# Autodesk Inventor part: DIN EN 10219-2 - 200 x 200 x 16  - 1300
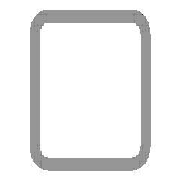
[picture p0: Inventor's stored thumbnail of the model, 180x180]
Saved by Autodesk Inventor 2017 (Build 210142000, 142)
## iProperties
Created: 2017-11
Part Number: DIN EN 10219-2 - 200 x 200 x 16  - 1300
Material: Steel, Mild
Description: Cold formed welded structural hollow sections of non-alloy and fine grain structural steel
Document SubType Name: Modeling
Standard: DIN
Designer: iusti
Standard Revision: 2006-07
Standards Organization: DIN
Language: en-US
Size Designation: 200 x 200 x 16
Categories: <MemberInstance><Categories><Category DisplayName="Structural Shapes" InternalName="089c4875-fa83-4c05-b084-43b9cc11f5ed" Mnemonic="GRDR"><CategoryParameter Dis
Stock Number: 200 x 200 x 16
Mass: 108961 g
Surface Area: 17564.1 cm^2
Volume: 13880.4 cm^3
Density: 7.85 g/cm^3
Appearance: Semi-Polished
_CCFamilyMember: 103
_CCFamilyDisplayName: DIN EN 10219-2 (Square Hollow Section - Cold Formed) - Cold formed welded structural hollow sections of non-alloy and fine grain structural steel
_FrameMemberDoc: Frame Member File
_Version: 15.0.0
_GetPNFromCC: 1
G_L: 1300.000 mm
G_W: 200.000 mm
G_H: 200.000 mm
+5245FDE4-FC26-48DD-8D5F-DB9AF3ABDA78+CUTDETAIL1: Cut
+5EC8F8CE-D404-4871-B3D9-14F147CC6C7E+CUTDETAIL2: Cut
IsCustomPart: 1
Author: iusti
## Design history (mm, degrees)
node "Start plane"
node "End plane"
sketch "Sketch"
  geometry: L1 (-100, -52)-(-100, 52); L2 (-52, 100)-(52, 100); L3 (100, 52)-(100, -52); L4 (52, -100)-(-52, -100); L5 (-52, 84)-(52, 84); L6 (84, 52)-(84, -52); L7 (52, -84)-(-52, -84); L8 (-84, -52)-(-84, 52); L9 (0, 153.918)-(0, -153.918) reference; L10 (-153.918, 0)-(153.918, 0) reference; A1 r 48 centre (-52, -52) between (-100, -52) and (-52, -100); A2 r 48 centre (-52, 52) between (-52, 100) and (-100, 52); A3 r 48 centre (52, 52) between (100, 52) and (52, 100); A4 r 48 centre (52, -52) between (52, -100) and (100, -52); A5 r 32 centre (-52, 52) between (-52, 84) and (-84, 52); A6 r 32 centre (52, 52) between (84, 52) and (52, 84); A7 r 32 centre (52, -52) between (52, -84) and (84, -52); A8 r 32 centre (-52, -52) between (-84, -52) and (-52, -84)
  constraints: 16 end point, 16 point on circle, 8 centre point, 8 tangent, 4 parallel, 3 equal radius, 2 perpendicular, 7 other
  dimensions: "d7" = 48 radius of A1 (= G_IR); "d10" = 200 distance between parallel lines of L2 L4 (= G_H); "d11" = 200 distance between parallel lines of L1 L3 (= G_W); "d12" = 16 distance between parallel lines of L3 L6 (= G_T); "d15" = 100 distance between parallel lines of L2 L10 (= 0.5 x d10); "d16" = 100 distance between parallel lines of L9 L3 (= 0.5 x d11)
extrude "Body" new body sketch "Sketch" stored distance "d3" = 1300 (= G_L); taper "d4" = 0 deg
node "Driven Length"
  sketch "Sketch3"
    geometry: L1 (0, 0)-(10, 0) reference
    constraints: 2 end point, 1 horizontal
  workplane "Work Plane3"
  sketch "Sketch4"
    geometry: L1 (-2, 100)-(12, 100) reference; L2 (-2, 1400)-(12, 1400) reference
    dimensions: "d18" = 1300 distance between parallel lines of L1 L2 (derived)
workplane "Work Plane4"
split "Split1"
workplane "Work Plane5"
split "Split2"
body "Solid1"
other parameters: "G_W" = 200 [user parameter; used in 1 equation term], "G_H" = 200 [user parameter; used in 1 equation term], "G_T" = 16 [user parameter; used in 1 equation term], "G_IR" = 48 [user parameter; used in 1 equation term], "G_L" = 1300 (= d18) [user parameter; used in 1 equation term], "d17" = 90 deg
